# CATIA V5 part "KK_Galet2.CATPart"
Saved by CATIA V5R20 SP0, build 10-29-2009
Part number: Galet1
Bounding box of the stored display mesh (mm): x 9 to 13.5, y 165.003 to 184.997, z -24.997 to -5.003
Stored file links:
  G:\Khaled_CFAO_2011\ST2M\ST2M_GR2\aandujar\Khaled\CAD_thinkMOTION\KK_Galet2.CATPart
  G:\Khaled_CFAO_2011\ST2M\ST2M_GR2\aandujar\Khaled\CAD_thinkMOTION\KK_Aandujar.CATProduct
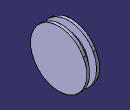
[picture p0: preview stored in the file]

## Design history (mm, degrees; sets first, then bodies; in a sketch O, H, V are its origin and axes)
WSupportSet1: ActiveGrid {3dwsupport RefPoint {point stored without definition}, 3DWOS ({wsupport Support xy-plane, RefPoint {3dwsupport}, GridIn {cartgrid Value 100, Stepbid1 0, Value 100, Stepbid2 0, Direction (1, 0, 0)}, GeometricData ({line type PtDir, Direction (1, 0, 0), Support xy-plane}; {line type PtDir, Direction (0, 1, 0), Support yz-plane})}; {wsupport Support yz-plane, RefPoint {3dwsupport}, GridIn {cartgrid Value 100, Stepbid1 0, Value 100, Stepbid2 0, Direction (0, 1, 0)}, GeometricData ({line type PtDir, Direction (0, 1, 0), Support yz-plane}; {line type PtDir, Direction (0, 0, 1), Support zx-plane})}; {wsupport Support zx-plane, RefPoint {3dwsupport}, GridIn {cartgrid Value 100, Stepbid1 0, Value 100, Stepbid2 0, Direction (0, 0, 1)}, GeometricData ({line type PtDir, Direction (0, 0, 1), Support zx-plane}; {line type PtDir, Direction (1, 0, 0), Support xy-plane})}), GeometricData ({line type PtDir, RefPoint {point stored without definition}, Direction (1, 0, 0), Support xy-plane}; {line type PtDir, RefPoint {point stored without definition}, Direction (0, 1, 0), Support yz-plane}; {line type PtDir, RefPoint {point stored without definition}, Direction (0, 0, 1), Support zx-plane})}
Set1
  Plane1: stored without definition
  Sketch1 on Plane1, origin (0, 0, -15), H (1, 0, 0), V (0, 1, 0)
    line L1 (13.5, 175) -> (9, 175)
    line L2 (9, 175) -> (9, 165)
    line L3 (9, 165) -> (10, 165)
    line L4 (10, 165) -> (10, 168)
    line L5 (10, 168) -> (12.5, 168)
    line L6 (12.5, 168) -> (12.5, 165)
    line L7 (12.5, 165) -> (13.5, 165)
    line L8 (13.5, 165) -> (13.5, 175)
    reference intersected line E1 through (12.5, 0) direction (0, 1) from Plane2
    reference projected line E2 (-7.5, 175) -> (32.5, 175) from Line1
    reference projected line E3 (-7.5, 175) -> (32.5, 175) from Line1
    reference projected line E4 (-7.5, 175) -> (32.5, 175) from Line1
    distance L8 L6 = 1
    distance L4 L2 = 1
    distance L6 L4 = 2.5
    distance L5 E3 = 7
    distance L7 E4 = 10
    horizontal: L1 H, L3 H, L5 H, L7 H
    vertical: L2 V, L4 V, L6 V, L8 V
    coincidence: E1 L6, E2 L1, L7 L3
Set2
  Plane2 "Plan.Ref5": linked copy from another document
  Line1 "Axe_pivot_galet1": linked copy from another document
Body1 (main body)
  Shaft1: profile Sketch1, axis Line1, angle 360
